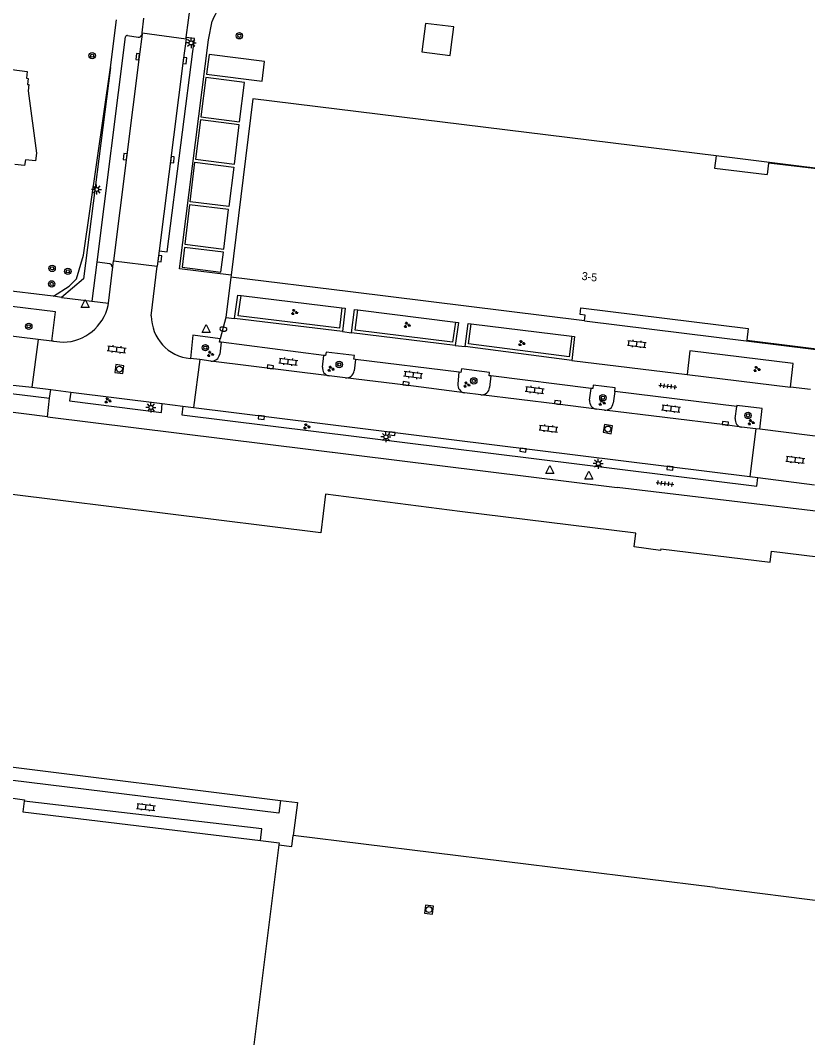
# Model space of a CAD drawing. Extents: x 131000 to 133014, y 396499 to 399001.
# Drawn here: x 131958.7 to 132057.1, y 397040.1 to 397167.2 of the extents above; entities that cross this region are included whole.
import ezdxf

# ---------------------------------------------------------------- set-up
doc = ezdxf.new("R2010")
doc.units = 0
for name, color, linetype in [('gg-afsc-hekwerk', 7, 'Continuous'), ('gg-anno-huisnummerreeks BGT', 7, 'Continuous'), ('gg-bbg-bijgebouw', 7, 'Continuous'), ('gg-bbg-gedigitaliseerde bebouwing', 7, 'Continuous'), ('gg-bbg-hoofdgebouw', 7, 'Continuous'), ('gg-bbg-luifel en loopbrug', 7, 'Continuous'), ('gg-bbg-onder overbouw', 7, 'Continuous'), ('gg-bbg-pand overbouw', 7, 'Continuous'), ('gg-knt-verharding', 7, 'Continuous'), ('gg-knt-verharding nz', 7, 'Continuous'), ('gt-grn-groengrens', 7, 'Continuous'), ('gt-grn-weggrens', 7, 'Continuous'), ('gt-symb-boom', 7, 'Continuous'), ('gt-symb-brandkraan', 7, 'Continuous'), ('gt-symb-groenvak', 7, 'Continuous'), ('gt-symb-klinker verharding', 7, 'Continuous'), ('gt-symb-kolk', 7, 'Continuous'), ('gt-symb-lichtmast', 7, 'Continuous'), ('gt-symb-rioolschacht', 7, 'Continuous'), ('gt-symb-tegel verharding', 7, 'Continuous'), ('gt-symb-waterafsluiter', 7, 'Continuous')]:
    doc.layers.add(name, color=color, linetype=linetype)

# ---------------------------------------------------------------- blocks, each defined once
blk = doc.blocks.new('gt0-KOLK')
at = {"layer": 'gt-symb-kolk'}
blk.add_lwpolyline([(0, 0), (0.38, 0), (0.38, 0.4), (-0.38, 0.4), (-0.38, 0), (0, 0)], dxfattribs=at)
blk = doc.blocks.new('gt0-LMAST')
at = {"layer": 'gt-symb-lichtmast'}
for p, q in [((-0.18, 0.17), (-0.45, 0.44)), ((-0.01, 0.25), (-0.01, 0.62)), ((0.17, 0.17), (0.44, 0.44)), ((-0.26, 0), (-0.63, 0)), ((-0.18, -0.18), (-0.45, -0.45)), ((-0.01, -0.25), (-0.01, -0.63)), ((0.44, -0.45), (0.17, -0.18)), ((0.24, 0), (0.62, 0))]:
    blk.add_line(p, q, dxfattribs=at)
blk.add_circle((-0.01, 0), 0.25, dxfattribs=at)
blk = doc.blocks.new('gt0-BOOM')
at = {"layer": 'gt-symb-boom'}
for radius in [0.4, 0.2]:
    blk.add_circle((0, 0), radius, dxfattribs=at)
blk = doc.blocks.new('gt0-WAFSL')
at = {"layer": 'gt-symb-waterafsluiter'}
for p, q in [((-0.5, -0.33), (0, 0.67)), ((0, 0.67), (0.5, -0.33)), ((0.5, -0.33), (-0.5, -0.33))]:
    blk.add_line(p, q, dxfattribs=at)
blk = doc.blocks.new('gt0-KL1')
at = {"layer": 'gt-symb-klinker verharding'}
for p, q in [((-1.15, 0.3), (1.15, 0.3)), ((-1, -0.3), (-1, 0.3)), ((-0.5, 0.3), (-0.5, 0.45)), ((0, -0.3), (0, 0.3)), ((0.5, 0.3), (0.5, 0.45)), ((1, -0.3), (1, 0.3)), ((-1.15, -0.3), (1.15, -0.3)), ((-0.5, -0.45), (-0.5, -0.3)), ((0.5, -0.45), (0.5, -0.3))]:
    blk.add_line(p, q, dxfattribs=at)
blk = doc.blocks.new('gt0-GRVAK')
at = {"layer": 'gt-symb-groenvak'}
for p, q in [((-0.11, 0.19), (-0.23, 0.24)), ((-0.18, 0.15), (0.09, 0.15)), ((-0.09, 0.21), (-0.16, 0.32)), ((-0.05, 0.21), (-0.05, 0.39)), ((0, 0.21), (0.06, 0.32)), ((0.02, 0.19), (0.13, 0.24)), ((0.26, -0.05), (0.2, 0.06)), ((0.3, -0.05), (0.3, 0.13)), ((0.35, -0.05), (0.41, 0.06)), ((-0.24, -0.23), (-0.36, -0.18)), ((-0.32, -0.26), (-0.05, -0.26)), ((-0.23, -0.21), (-0.29, -0.09)), ((-0.18, -0.2), (-0.18, -0.02)), ((-0.14, -0.21), (-0.07, -0.09)), ((-0.12, -0.23), (0, -0.18)), ((0.24, -0.07), (0.12, -0.02)), ((0.17, -0.11), (0.44, -0.11)), ((0.37, -0.07), (0.49, -0.02))]:
    blk.add_line(p, q, dxfattribs=at)
blk = doc.blocks.new('gt0-BR')
at = {"layer": 'gt-symb-brandkraan'}
for centre, radius, start, end in [((-0.24, 0), 0.206, 107.5669, 252.4331), ((0.6, -2.66), 3, 106.892, 107.5669), ((0, -0.69), 0.938, 73.108, 106.892), ((-0.6, -2.66), 3, 72.4331, 73.108), ((0.24, 0), 0.206, 287.567, 72.4331), ((0.6, 2.66), 3, 252.4331, 253.108), ((0, 0.69), 0.938, 253.108, 286.8921), ((-0.6, 2.66), 3, 286.8921, 287.567)]:
    blk.add_arc(centre, radius, start, end, dxfattribs=at)
blk = doc.blocks.new('gt0-RS')
at = {"layer": 'gt-symb-rioolschacht'}
blk.add_lwpolyline([(-0.5, -0.5), (0.5, -0.5), (0.5, 0.5), (-0.5, 0.5)], close=True, dxfattribs=at)
blk.add_circle((0, 0), 0.375, dxfattribs=at)
blk = doc.blocks.new('gt0-TEG1')
at = {"layer": 'gt-symb-tegel verharding'}
for p, q in [((-1.12, 0), (1.12, 0)), ((-0.9, -0.25), (-0.9, 0.25)), ((-0.45, -0.25), (-0.45, 0.25)), ((0, -0.25), (0, 0.25)), ((0.45, -0.25), (0.45, 0.25)), ((0.9, -0.25), (0.9, 0.25))]:
    blk.add_line(p, q, dxfattribs=at)

msp = doc.modelspace()

# ---------------------------------------------------------------- linework, layer by layer
at = {"layer": 'gg-afsc-hekwerk'}
for p, q in [((131982.24, 397164.8), (131982.69, 397167.14)), ((131978.62, 397136.2), (131982.24, 397164.8)), ((131985.06, 397135.42), (131978.62, 397136.2)), ((131959.21, 397069.67), (131959.05, 397068.32)), ((131959.05, 397068.32), (131988.72, 397064.75)), ((131991.05, 397064.21), (131986.56, 397028.3))]:
    msp.add_line(p, q, dxfattribs=at)
for points in [[(131953.2, 397069.02), (131953.39, 397070.59), (131956.28, 397070.24), (131959.24, 397069.83), (131959.21, 397069.67)], [(131988.72, 397064.75), (131991.08, 397064.47), (131991.05, 397064.21)]]:
    msp.add_lwpolyline(points, dxfattribs=at)
msp.add_arc((131987.91, 397165.29), 5.54, 87.6307, 160.5173, dxfattribs=at)
at = {"layer": 'gg-bbg-bijgebouw'}
msp.add_lwpolyline([(132012.58, 397163.89), (132012.91, 397166.42), (132009.36, 397166.87), (132008.9, 397163.3), (132012.45, 397162.85), (132012.58, 397163.89)], dxfattribs=at)
at = {"layer": 'gg-bbg-gedigitaliseerde bebouwing'}
for p, q in [((131993.36, 397069.5), (131992.83, 397065.38)), ((132045.59, 397058.88), (131992.83, 397065.38)), ((132045.59, 397058.88), (132062.99, 397056.68))]:
    msp.add_line(p, q, dxfattribs=at)
at = {"layer": 'gg-bbg-hoofdgebouw'}
for p, q in [((131985.06, 397135.42), (131985.03, 397135.15)), ((132038.77, 397101.21), (132038.75, 397101)), ((131955.18, 397074.25), (131991.24, 397069.76)), ((131991.24, 397069.76), (131993.36, 397069.5))]:
    msp.add_line(p, q, dxfattribs=at)
for points in [[(131957.66, 397161.09), (131959.59, 397160.84), (131959.49, 397160.02), (131959.69, 397160), (131959.61, 397159.25), (131959.77, 397159.22), (131959.71, 397158.44), (131960.76, 397150.67), (131960.63, 397149.68), (131959.38, 397149.83), (131959.24, 397149.12), (131958.02, 397149.24)], [(132045.69, 397150.32), (131987.79, 397157.46), (131985.06, 397135.42)], [(132029.22, 397129.71), (132000, 397133.3), (131985.03, 397135.15)], [(131996.27, 397103.19), (131957.36, 397108.02), (131957.34, 397108.19), (131956.81, 397108.23), (131956.38, 397104.91)], [(132013.66, 397105.88), (131996.87, 397108.05), (131996.27, 397103.19)], [(132038.75, 397101), (132035.45, 397101.46), (132035.66, 397103.16), (132013.66, 397105.88)], [(132038.77, 397101.21), (132052.45, 397099.53), (132052.62, 397100.9), (132078.5, 397097.73), (132077, 397085.54), (132074, 397085.91), (132073.79, 397084.19), (132074.91, 397084.05), (132071.9, 397059.65)]]:
    msp.add_lwpolyline(points, dxfattribs=at)
at = {"layer": 'gg-bbg-luifel en loopbrug'}
for points in [[(131982.31, 397162.99), (131982, 397160.51), (131988.94, 397159.63), (131989.26, 397162.11), (131982.31, 397162.99)], [(131981.27, 397155.19), (131986.13, 397154.57), (131986.76, 397159.5), (131981.9, 397160.12), (131981.27, 397155.19)], [(131980.61, 397149.88), (131985.48, 397149.27), (131986.09, 397154.21), (131981.23, 397154.82), (131980.61, 397149.88)], [(131979.93, 397144.58), (131980.55, 397149.51), (131985.41, 397148.9), (131984.79, 397143.97), (131979.93, 397144.58)], [(131979.28, 397139.26), (131984.14, 397138.67), (131984.75, 397143.61), (131979.88, 397144.21), (131979.28, 397139.26)], [(131979.23, 397138.88), (131978.94, 397136.4), (131983.79, 397135.79), (131984.1, 397138.27), (131979.23, 397138.88)]]:
    msp.add_lwpolyline(points, dxfattribs=at)
at = {"layer": 'gg-bbg-onder overbouw'}
for points in [[(132045.69, 397150.32), (132045.49, 397148.78), (132052.08, 397147.98)], [(132028.78, 397131.31), (132049.7, 397128.73), (132049.52, 397127.27), (132062.28, 397125.68), (132063.45, 397135.21), (132064.82, 397135.05), (132065.43, 397139.99), (132065.57, 397139.98), (132065.61, 397140.32), (132065.47, 397140.34), (132065.74, 397142.7), (132058.71, 397143.57), (132059.34, 397148.55), (132052.25, 397149.42), (132052.08, 397147.98)], [(132029.22, 397129.71), (132029.31, 397130.41), (132028.68, 397130.49), (132028.78, 397131.31)]]:
    msp.add_lwpolyline(points, dxfattribs=at)
at = {"layer": 'gg-bbg-pand overbouw'}
for points in [[(132065.99, 397125.42), (132066.03, 397125.67), (132066.73, 397125.58), (132066.94, 397127.2), (132066.23, 397127.29), (132066.7, 397131.04), (132067.4, 397130.95), (132067.59, 397132.58), (132066.9, 397132.69), (132067.78, 397139.97), (132068.5, 397139.88), (132068.69, 397141.5), (132067.99, 397141.58), (132068.46, 397145.32), (132069.17, 397145.25), (132069.37, 397146.88), (132068.67, 397146.97), (132068.72, 397147.46), (132045.69, 397150.32)], [(132029.22, 397129.71), (132065.96, 397125.15), (132065.99, 397125.42)]]:
    msp.add_lwpolyline(points, dxfattribs=at)
at = {"layer": 'gg-knt-verharding'}
for p, q in [((131979.46, 397165.12), (131980.04, 397169.44)), ((131973.95, 397165.67), (131974.17, 397167.52)), ((131969.97, 397161.37), (131970.72, 397167.31)), ((131968.32, 397137.01), (131971.87, 397165.19)), ((131972.1, 397165.36), (131973.44, 397165.16)), ((131973.93, 397165.52), (131973.95, 397165.67)), ((131973.95, 397165.67), (131979.44, 397164.93)), ((131979.44, 397164.93), (131979.46, 397165.12)), ((131976.08, 397138.44), (131975.84, 397136.51)), ((131962.82, 397132.76), (131927.12, 397137.12)), ((131969.9, 397136.8), (131968.32, 397137.01)), ((131970.29, 397136.46), (131970.38, 397137.18)), ((131970.38, 397137.18), (131975.84, 397136.51)), ((131969.72, 397131.91), (131970.29, 397136.46)), ((131970.15, 397136.48), (131970.29, 397136.46)), ((131975.09, 397130.33), (131975.84, 397136.51)), ((131985.03, 397135.15), (131984.41, 397130.12)), ((131962.86, 397132.76), (131962.82, 397132.76)), ((131963.85, 397132.63), (131962.86, 397132.76)), ((131967.64, 397132.17), (131969.72, 397131.91)), ((131969.69, 397131.63), (131969.72, 397131.91)), ((131986.31, 397132.87), (131998.92, 397131.33)), ((132000.9, 397131.07), (132013.1, 397129.55)), ((131984.41, 397130.12), (131985.47, 397130)), ((131998.97, 397128.36), (131985.47, 397130)), ((132015.07, 397129.32), (132027.64, 397127.77)), ((131960.95, 397127.38), (131946.23, 397129.14)), ((131998.97, 397128.36), (132000.12, 397128.21)), ((132013.08, 397126.61), (132000.12, 397128.21)), ((131960.95, 397127.38), (131960.16, 397121.39)), ((131962.64, 397127.16), (131960.95, 397127.38)), ((131962.86, 397127.14), (131962.64, 397127.16)), ((131962.86, 397127.14), (131964.07, 397127.04)), ((131983.84, 397127.01), (131983.64, 397125.51)), ((131996.67, 397125.38), (131983.84, 397127.01)), ((132013.08, 397126.61), (132014.32, 397126.48)), ((132027.67, 397124.73), (132014.32, 397126.48)), ((131981.14, 397124.86), (131979.97, 397124.98)), ((131981.14, 397124.86), (131980.38, 397118.87)), ((131982.53, 397124.66), (131981.14, 397124.86)), ((131996.49, 397123.92), (131996.67, 397125.38)), ((132000.61, 397124.88), (132000.44, 397123.46)), ((132013.59, 397123.27), (132000.61, 397124.88)), ((132027.67, 397124.73), (132042.06, 397122.98)), ((132013.43, 397121.81), (132013.59, 397123.27)), ((132042.06, 397122.98), (132054.98, 397121.42)), ((131999.34, 397122.56), (131997.32, 397122.82)), ((132017.55, 397122.81), (132017.37, 397121.37)), ((132030.06, 397121.25), (132017.55, 397122.81)), ((131953.67, 397121.09), (131962.36, 397120.03)), ((131960.16, 397121.39), (131962.54, 397121.1)), ((131962.36, 397120.03), (131962.54, 397121.1)), ((131962.54, 397121.1), (131965.03, 397120.77)), ((131965.03, 397120.77), (131976.46, 397119.35)), ((132016.28, 397120.46), (132014.23, 397120.71)), ((132029.88, 397119.78), (132030.06, 397121.25)), ((132033.03, 397120.88), (132032.84, 397119.41)), ((132048.27, 397118.99), (132033.03, 397120.88)), ((132057.49, 397121.1), (132054.98, 397121.42)), ((131976.46, 397119.35), (131979.03, 397119.02)), ((131962.13, 397117.7), (131951.01, 397119.08)), ((131979.03, 397119.02), (131980.38, 397118.87)), ((131980.38, 397118.87), (132049.92, 397110.23)), ((132031.72, 397118.54), (132030.72, 397118.66)), ((132048.09, 397117.5), (132048.27, 397118.99)), ((131962.13, 397117.7), (132033.31, 397108.86)), ((132050.66, 397116.2), (132048.86, 397116.39)), ((132050.66, 397116.2), (132049.92, 397110.23)), ((132051.14, 397116.14), (132050.66, 397116.2)), ((132060.26, 397115), (132051.14, 397116.14)), ((132049.92, 397110.23), (132050.89, 397110.12)), ((132050.89, 397110.12), (132058.01, 397109.2))]:
    msp.add_line(p, q, dxfattribs=at)
for points in [[(131976.08, 397138.44), (131977.09, 397138.32), (131980.49, 397164.99), (131979.46, 397165.12)], [(131979.44, 397164.93), (131979.08, 397162.24), (131976.08, 397138.44)], [(131969.97, 397161.37), (131966.63, 397134.93), (131963.85, 397132.63)], [(131968.32, 397137.01), (131968.27, 397137.02), (131967.64, 397132.17)], [(131962.64, 397127.16), (131963.11, 397130.83), (131946.7, 397132.84), (131946.23, 397129.14)], [(131985.47, 397130), (131985.91, 397132.92), (131986.31, 397132.87)], [(131998.92, 397131.33), (131999.32, 397131.28), (131998.97, 397128.36)], [(132000.12, 397128.21), (132000.51, 397131.12), (132000.9, 397131.07)], [(132013.1, 397129.55), (132013.5, 397129.5), (132013.08, 397126.61)], [(132014.32, 397126.48), (132014.7, 397129.36), (132015.07, 397129.32)], [(131983.68, 397127.45), (131980.27, 397127.89), (131979.97, 397124.98)], [(131983.84, 397127.01), (131983.62, 397127.02), (131983.68, 397127.45)], [(132027.64, 397127.77), (132028, 397127.73), (132027.67, 397124.73)], [(132000.61, 397124.88), (132000.4, 397124.91), (132000.48, 397125.38), (131996.93, 397125.8), (131996.88, 397125.38), (131996.67, 397125.38)], [(132054.98, 397121.42), (132055.33, 397124.37), (132042.39, 397125.96), (132042.06, 397122.98)], [(132017.55, 397122.81), (132017.33, 397122.83), (132017.38, 397123.26), (132013.87, 397123.69), (132013.8, 397123.25), (132013.59, 397123.27)], [(131953.8, 397122.14), (131956.61, 397121.79), (131960.16, 397121.39)], [(131965.03, 397120.77), (131964.88, 397119.69), (131976.36, 397118.24), (131976.46, 397119.35)], [(132033.03, 397120.88), (132033.09, 397121.33), (132030.34, 397121.64), (132030.27, 397121.22), (132030.06, 397121.25)], [(132051.14, 397116.14), (132051.44, 397118.74), (132048.29, 397119.13), (132048.27, 397118.99)], [(131979.03, 397119.02), (131978.9, 397117.93), (132050.78, 397109.02), (132050.89, 397110.12)], [(132084.17, 397102.79), (132081.77, 397103.06), (132073.87, 397104.03), (132033.31, 397108.86)], [(131991.24, 397069.76), (131991.02, 397068.15), (131955.02, 397072.58), (131955.18, 397074.25)], [(131988.72, 397064.75), (131988.91, 397066.19), (131959.21, 397069.67)], [(131991.05, 397064.21), (131992.65, 397064), (131992.83, 397065.38)]]:
    msp.add_lwpolyline(points, dxfattribs=at)
for centre, radius, start, end in [((131972.07, 397165.17), 0.195, 79.1913, 174.4691), ((131973.51, 397165.57), 0.421, 260.1986, 353.1661), ((131969.87, 397136.51), 0.289, 353.1905, 83.517), ((131963.99, 397132.86), 5.83, 270.7878, 347.7899), ((131980.46, 397130.33), 5.37, 180.0109, 264.8291), ((131982.64, 397125.67), 1.01, 263.4144, 350.9483), ((131997.46, 397123.79), 0.983, 172.4542, 261.8491), ((131999.45, 397123.55), 0.991, 263.9329, 354.931), ((132014.39, 397121.67), 0.976, 171.5749, 260.523), ((132016.38, 397121.45), 0.999, 264.1584, 355.0095), ((132030.87, 397119.65), 0.999, 172.3541, 261.5981), ((132031.84, 397119.55), 1.01, 263.2532, 352.5393), ((132049.04, 397117.34), 0.964, 170.3004, 258.9445)]:
    msp.add_arc(centre, radius, start, end, dxfattribs=at)
at = {"layer": 'gg-knt-verharding nz'}
msp.add_line((131997.32, 397122.82), (131982.53, 397124.66), dxfattribs=at)
for points in [[(131973.93, 397165.52), (131973.59, 397162.68), (131970.38, 397137.18)], [(132014.23, 397120.71), (132006.9, 397121.65), (131999.34, 397122.56)], [(132030.72, 397118.66), (132025.87, 397119.3), (132016.28, 397120.46)], [(132048.86, 397116.39), (132046.82, 397116.68), (132031.72, 397118.54)]]:
    msp.add_lwpolyline(points, dxfattribs=at)
at = {"layer": 'gt-grn-groengrens'}
for points in [[(131962.86, 397132.76), (131964.83, 397134.03), (131965.76, 397134.96), (131966.63, 397137.89), (131969.97, 397161.37)], [(131998.92, 397131.33), (131998.62, 397128.8), (131985.93, 397130.34), (131986.31, 397132.87)], [(132013.1, 397129.55), (132012.74, 397127.05), (132000.57, 397128.55), (132000.9, 397131.07)], [(132027.64, 397127.77), (132027.32, 397125.18), (132014.76, 397126.82), (132015.07, 397129.32)]]:
    msp.add_lwpolyline(points, dxfattribs=at)
at = {"layer": 'gt-grn-weggrens'}
for p, q in [((131963.85, 397132.63), (131967.64, 397132.17)), ((131984.41, 397130.12), (131983.68, 397127.45)), ((131962.13, 397117.7), (131962.36, 397120.03))]:
    msp.add_line(p, q, dxfattribs=at)

# ---------------------------------------------------------------- block references
at = {"layer": 'gt-symb-boom'}
for p in [(131986.1, 397165.32), (131967.7, 397162.83), (131962.69, 397136.25), (131964.66, 397135.88), (131962.64, 397134.31), (131959.77, 397129.01), (131981.85, 397126.34), (131998.58, 397124.24), (132015.4, 397122.19), (132031.54, 397120.08), (132049.68, 397117.87)]:
    msp.add_blockref('gt0-BOOM', p, dxfattribs=at)
at = {"layer": 'gt-symb-brandkraan', "rotation": 173.05258934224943}
msp.add_blockref('gt0-BR', (131984.1, 397128.66), dxfattribs=at)
at = {"layer": 'gt-symb-groenvak'}
for p in [(131992.96, 397130.78), (132007.04, 397129.18), (132021.36, 397126.9), (131982.46, 397125.54), (131997.52, 397123.69), (132050.76, 397123.66), (132014.5, 397121.71), (131969.64, 397119.73), (132031.41, 397119.46), (131994.48, 397116.49), (132050.04, 397117.02)]:
    msp.add_blockref('gt0-GRVAK', p, dxfattribs=at)
at = {"layer": 'gt-symb-klinker verharding'}
for p, rotation in [((132035.78, 397126.81), -6.719879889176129), ((131970.77, 397126.13), -7.0042592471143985), ((131992.21, 397124.6), -7.181878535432), ((132007.8, 397122.92), 172.70443985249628), ((132023.02, 397121.05), -7.00425924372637), ((132040.06, 397118.74), -7.00425924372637), ((132024.74, 397116.23), -7.0042592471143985), ((132055.59, 397112.33), -7.004259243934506), ((131974.42, 397068.93), -6.662963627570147)]:
    msp.add_blockref('gt0-KL1', p, dxfattribs=dict(at, rotation=rotation))
at = {"layer": 'gt-symb-kolk'}
for p, rotation in [((131973.59, 397162.68), 84.00113167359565), ((131979.08, 397162.24), -95.99886832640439), ((131972.03, 397150.19), 84.00113167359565), ((131977.53, 397149.87), -95.99886832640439), ((131975.96, 397137.48), -95.99886832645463), ((131989.94, 397123.74), -7.181878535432), ((132006.9, 397121.65), -7.295560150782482), ((132025.87, 397119.3), -7.465974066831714), ((131988.87, 397117.81), 172.8749836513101), ((132046.82, 397116.68), -8.049061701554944), ((132005.21, 397115.79), 173.57125225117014), ((132021.58, 397113.74), 172.8749836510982), ((132039.94, 397111.48), 172.93185995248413)]:
    msp.add_blockref('gt0-KOLK', p, dxfattribs=dict(at, rotation=rotation))
at = {"layer": 'gt-symb-lichtmast'}
for p in [(131980.08, 397164.42), (131968.26, 397146.12), (131975.05, 397118.87), (132004.43, 397115.18), (132030.96, 397111.85)]:
    msp.add_blockref('gt0-LMAST', p, dxfattribs=at)
at = {"layer": 'gt-symb-rioolschacht'}
for p, rotation in [((131971.11, 397123.66), -97.29556014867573), ((132032.16, 397116.17), 79.51061018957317), ((132009.8, 397056.12), 82.46974665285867)]:
    msp.add_blockref('gt0-RS', p, dxfattribs=dict(at, rotation=rotation))
at = {"layer": 'gt-symb-tegel verharding'}
for p, rotation in [((132039.65, 397121.53), -6.890548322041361), ((132039.31, 397109.37), -7.068140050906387)]:
    msp.add_blockref('gt0-TEG1', p, dxfattribs=dict(at, rotation=rotation))
at = {"layer": 'gt-symb-waterafsluiter'}
for p in [(131966.81, 397131.7), (131981.94, 397128.56), (132024.92, 397110.95), (132029.79, 397110.23)]:
    msp.add_blockref('gt0-WAFSL', p, dxfattribs=at)

# ---------------------------------------------------------------- texts
at = {"layer": 'gg-anno-huisnummerreeks BGT'}
msp.add_text('3-5', height=1, rotation=352.9, dxfattribs=at).set_placement((132028.84, 397134.83))

doc.saveas('drawing.dxf')
